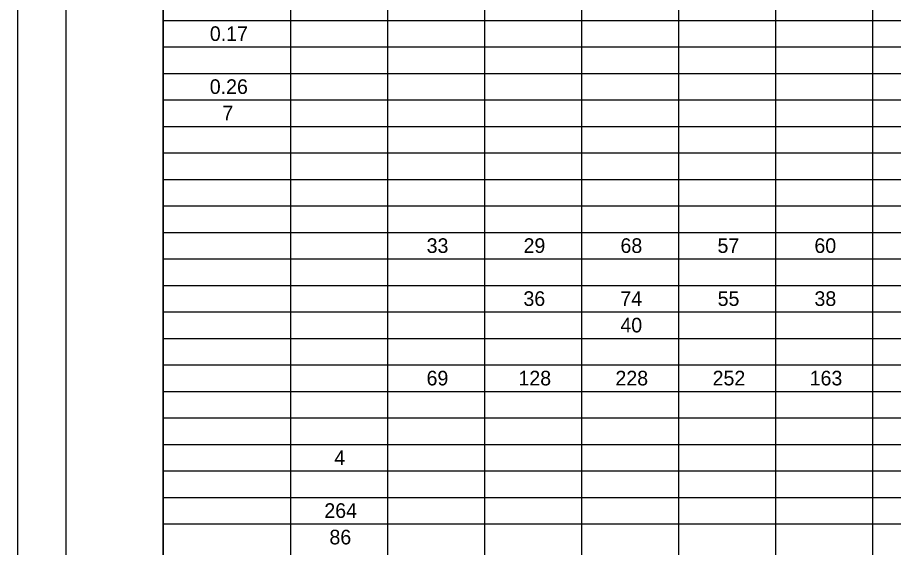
# Model space of a CAD drawing. Extents: x 0 to 34, y 0 to 22.
# Drawn here: x 0 to 9.02, y 10.89 to 16.35 of the extents above; entities that cross this region are included whole.
import ezdxf

# ---------------------------------------------------------------- set-up
doc = ezdxf.new("R2010")
doc.units = 0
for name, color, linetype in [('Default', 7, 'Continuous'), ('SH_Border', 7, 'Continuous'), ('SH_Cut_Line', 7, 'Continuous')]:
    doc.layers.add(name, color=color, linetype=linetype)

msp = doc.modelspace()

# ---------------------------------------------------------------- linework, layer by layer
at = {"layer": 'Default'}
for p, q in [((1.5, 21.5), (1.5, 1.0467)), ((2.8104, 20.9546), (2.8104, 1.0467)), ((3.8088, 20.9546), (3.8088, 1.0467)), ((4.8072, 20.9546), (4.8072, 1.0467)), ((5.8056, 20.9546), (5.8056, 1.0467)), ((6.804, 20.9546), (6.804, 1.0467)), ((7.8024, 20.9546), (7.8024, 1.0467)), ((8.8008, 20.9546), (8.8008, 1.0467)), ((1.5, 16.3185), (31.9928, 16.3185)), ((1.5, 16.0458), (31.9928, 16.0458)), ((1.5, 15.7731), (31.9928, 15.7731)), ((1.5, 15.5004), (31.9928, 15.5004)), ((1.5, 15.2276), (31.9928, 15.2276)), ((1.5, 14.9549), (31.9928, 14.9549)), ((1.5, 14.6822), (31.9928, 14.6822)), ((1.5, 14.4095), (31.9928, 14.4095)), ((1.5, 14.1368), (31.9928, 14.1368)), ((1.5, 13.8641), (31.9928, 13.8641)), ((1.5, 13.5914), (31.9928, 13.5914)), ((1.5, 13.3187), (31.9928, 13.3187)), ((1.5, 13.046), (31.9928, 13.046)), ((1.5, 12.7732), (31.9928, 12.7732)), ((1.5, 12.5005), (31.9928, 12.5005)), ((1.5, 12.2278), (31.9928, 12.2278)), ((1.5, 11.9551), (31.9928, 11.9551)), ((1.5, 11.6824), (31.9928, 11.6824)), ((1.5, 11.4097), (31.9928, 11.4097)), ((1.5, 11.137), (31.9928, 11.137))]:
    msp.add_line(p, q, dxfattribs=at)
at = {"layer": 'SH_Border'}
for points in [[(0.5, 21.5), (1.5, 21.5), (1.5, 0.5), (0.5, 0.5)], [(1.5, 21.5), (33.5, 21.5), (33.5, 0.5), (1.5, 0.5)]]:
    msp.add_lwpolyline(points, close=True, dxfattribs=at)
at = {"layer": 'SH_Cut_Line'}
msp.add_lwpolyline([(0, 0), (34, 0), (34, 22), (0, 22)], close=True, dxfattribs=at)

# ---------------------------------------------------------------- texts
at = {"layer": 'Default'}
for s, height, p in [('0.17', 0.15054, (1.9795, 16.1069)), ('0.26', 0.15054, (1.9789, 15.5614)), ('7', 0.1505, (2.1083, 15.2887)), ('33', 0.15054, (4.2111, 13.9252)), ('29', 0.15054, (5.2085, 13.9252)), ('68', 0.15054, (6.2059, 13.9252)), ('57', 0.15054, (7.2048, 13.9252)), ('60', 0.15054, (8.202, 13.9252)), ('36', 0.15054, (5.2073, 13.3798)), ('74', 0.15054, (6.2046, 13.3798)), ('55', 0.15054, (7.2061, 13.3798)), ('38', 0.15054, (8.2027, 13.3798)), ('40', 0.15054, (6.2052, 13.107)), ('69', 0.15054, (4.2101, 12.5616)), ('128', 0.15054, (5.1559, 12.5616)), ('228', 0.15054, (6.1543, 12.5616)), ('252', 0.15054, (7.1542, 12.5616)), ('163', 0.15054, (8.1531, 12.5616)), ('4', 0.1505, (3.261, 11.7435)), ('264', 0.15054, (3.1579, 11.1981)), ('86', 0.15054, (3.2105, 10.9254))]:
    msp.add_text(s, height=height, dxfattribs=at).set_placement(p)

doc.saveas('drawing.dxf')
